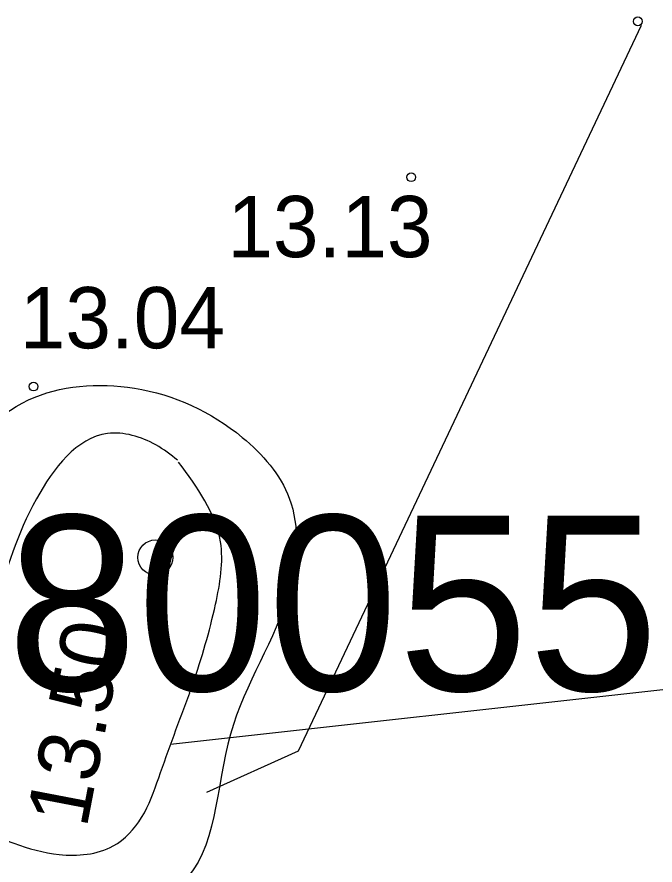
# Model space of a CAD drawing. Extents: x 503877 to 504025, y 304562 to 304725.
# Drawn here: x 503925.74 to 503933.02, y 304712.31 to 304722 of the extents above; entities that cross this region are included whole.
import ezdxf

# ---------------------------------------------------------------- set-up
doc = ezdxf.new("R2010")
doc.units = 0
for name, color, linetype in [('24', 7, 'Continuous'), ('Level 31', 7, 'Continuous'), ('NORB_ELEM_####_####_#', 7, 'Continuous'), ('NORB_ZOGS_SBST_####_#', 7, 'Continuous'), ('RELJ_AATZ_####_TKST_#', 7, 'Continuous'), ('RELJ_ELEM_####_####_#', 7, 'Continuous'), ('RELJ_NOGA_####_####_#', 7, 'Continuous'), ('SKAN_VADP_PAST_####_#', 7, 'Continuous')]:
    doc.layers.add(name, color=color, linetype=linetype)

msp = doc.modelspace()

# ---------------------------------------------------------------- linework, layer by layer
at = {"layer": 'Level 31'}
msp.add_circle((503927.315, 304715.827), 0.2, dxfattribs=at)
msp.add_spline([(503924.5, 304712.506), (503925.172, 304712.013), (503926.717, 304711.766), (503927.613, 304712.102), (503928.173, 304713.809), (503928.845, 304715.448), (503928.845, 304716.503), (503928.308, 304717.199), (503927.076, 304717.761), (503925.866, 304717.626), (503924.522, 304715.425), (503924.41, 304713.135), (503924.5, 304712.506)], degree=3, dxfattribs=at)
at = {"layer": 'NORB_ELEM_####_####_#'}
msp.add_line((503928.946, 304713.614), (503927.899, 304713.142), dxfattribs=at)
at = {"layer": 'NORB_ZOGS_SBST_####_#'}
msp.add_line((503932.862, 304721.904), (503928.946, 304713.614), dxfattribs=at)
at = {"layer": 'RELJ_ELEM_####_####_#'}
for centre in [(503932.823, 304721.951), (503930.237, 304720.17), (503925.926, 304717.779)]:
    msp.add_circle(centre, 0.05, dxfattribs=at)
at = {"layer": 'RELJ_NOGA_####_####_#'}
for points in [[(503927.5695, 304716.9392), (503927.3219, 304717.1123), (503926.7701, 304717.2423), (503925.9586, 304716.4951), (503925.5041, 304715.293), (503925.1795, 304713.8961), (503925.2444, 304712.824), (503925.6989, 304712.5641), (503926.2183, 304712.4342), (503926.835, 304712.5317), (503927.1596, 304712.8565), (503927.3544, 304713.3113), (503927.7079, 304714.2798)], [(503927.7074, 304714.2791), (503927.7434, 304714.3827), (503928.0031, 304715.2923), (503928.06, 304716.0052), (503927.5811, 304716.9167)]]:
    msp.add_spline(points, degree=3, dxfattribs=at)
at = {"layer": 'SKAN_VADP_PAST_####_#'}
msp.add_line((503935.031, 304714.53), (503927.488, 304713.689), dxfattribs=at)

# ---------------------------------------------------------------- texts
at = {"layer": '24'}
msp.add_text('80760080055', height=1.999998, dxfattribs=at).set_placement((503916.698, 304714.306))
at = {"layer": 'RELJ_AATZ_####_TKST_#'}
for s, p in [('13.13', (503928.137, 304719.257)), ('13.04', (503925.768, 304718.216))]:
    msp.add_text(s, height=0.7, dxfattribs=at).set_placement(p)
msp.add_text('13.50', height=0.7, rotation=79.13214, dxfattribs=at).set_placement((503926.53, 304712.724))

doc.saveas('drawing.dxf')
